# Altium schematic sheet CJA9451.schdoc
size 127 x 101 mm
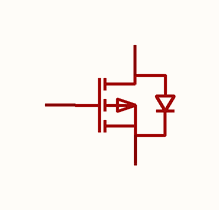
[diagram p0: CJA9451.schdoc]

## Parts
Q?  cja9451  [SOT-89-3_L4.5-W2.5-P1.50-LS4.2-BR]  (value not drawn)

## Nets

Not connected (* = marked no-connect by the designer): Q? 1(G) 2(D) 3(S)

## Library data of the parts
Q? = cja9451: 数量:1个P沟道;漏源电压(Vdss):20V;连续漏极电流(Id):2.3A;导通电阻(RDS(on)):135mΩ@4.5V;耗散功率(Pd):500mW;阈值电压(Vgs(th)):1.5V;; Manufacturer: CJ(江苏长电/长晶); AddInBom: yes; ModelId: 6db690b7897d4d18a30d90c1b89525ee; ModelName: SOT-89-3_L4.3-W2.5-H1.6-LS4.1-P1.50; ModelTransform: 161.417,169.291,0,180,0,0,-18.661,0,0; Number: 1个P沟道; Drain to Source Voltage: 20V; Current - Continuous Drain(Id): 2.3A; Pd - Power Dissipation: 500mW; Gate Threshold Voltage (Vgs(th)): 1.5V; Input Capacitance(Ciss): 430pF; Reverse Transfer Capacitance (Crss@Vds): 35pF; Type: P沟道; Output Capacitance(Coss): 100pF; Vgs: ±12V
